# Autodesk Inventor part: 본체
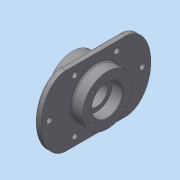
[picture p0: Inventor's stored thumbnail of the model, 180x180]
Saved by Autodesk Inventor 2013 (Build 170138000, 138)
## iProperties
Created: 2015-02
Part Number: 본체
Material: 일반
Document SubType Name: Modeling
Designer: Administrator
Density: 1 g/cm^3
Author: Administrator
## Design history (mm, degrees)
sketch "스케치1" dims "d51" = 50
  geometry: L1 (-154, 0)-(154, 0) reference; L2 (0, -98)-(0, 98) reference; L3 (60, 70)-(-60, 70); L4 (-60, 70)-(-60, -70); L5 (-60, -70)-(60, -70); L6 (60, -70)-(60, 70); 3 further points; 2 other entities
  constraints: 8 end point, 2 parallel, 2 vertical, 1 horizontal, 1 midpoint, 1 perpendicular, 1 symmetric about line, 10 other
  dimensions: "d1" = 140 distance of L4.end L3.end; "d3" = 120 distance between parallel lines of L4 L6
extrude "돌출1" new body sketch "스케치1" distance "d5" = 12; taper "d6" = 0 deg
sketch "스케치2"
  geometry: C1 r 50 at (0, 0); 1 further point
  constraints: 1 centre point, 1 coincident
  dimensions: "d7" = 100 diameter of C1
extrude "돌출2" join sketch "스케치2" distance "d9" = 23; taper "d11" = 0 deg; dims "d10" = 47, "d12" = 0
sketch "스케치3"
  geometry: L1 (0, 60)-(0, -60) reference; L2 (-35, 0)-(-35, 31); L3 (-35, 31)-(-13, 31); L4 (-13, 31)-(-13, 22.5); L5 (-13, 22.5)-(13, 22.5); L6 (13, 22.5)-(13, 31); L7 (13, 31)-(35, 31); L8 (35, 31)-(35, 0); L9 (-35, 50)-(-35, -50) reference; L10 (35, -50)-(35, 50) reference; 7 further points
  constraints: 14 end point, 4 midpoint, 3 parallel, 3 vertical, 2 point on line, 2 vertical alignment, 1 collinear, 1 perpendicular, 6 other
  dimensions: "d13" = 22 distance between parallel lines of L8 L6; "d15" = 22 distance between parallel lines of L4 L2; "d16" = 62 dimension on L3; "d17" = 62 dimension on L7; "d18" = 45 dimension on L5
revolve "회전1" sketch "스케치3" stored, may be unused: angle "d19" = 90 deg
sketch "스케치6" dims "d34" = 82
  geometry: L1 (0, 0)-(-28.991, 28.991); L2 (-98, 0)-(98, 0) reference; C1 r 50 at (0, 0) reference; 1 further point
  constraints: 2 coincident, 2 end point, 3 other
  dimensions: "d36" = 45 deg angle of L2 L1
hole "구멍1" sketch "스케치6" at (-28.991, 28.991) diameter "d38" = 4.917; stored, may be unused: countersink angle "d42" = 90 deg, drill point angle "d44" = 118 deg; dims "d39" = 10, "d40" = 4, "d41" = 2, "d43" = 13
node "작업 평면1"
sketch "스케치8" dims "d53" = 17
  geometry: L1 (70, 60)-(70, -60) reference; L2 (-70, -60)-(-70, 60) reference; L3 (53, 60)-(53, -60); L4 (-53, -60)-(-53, 60); L5 (0, -154)-(0, 154) reference; L6 (-98, 0)-(98, 0) reference; L7 (-82.976, 42)-(82.976, 42); C1 r 10 at (0, 93); C2 r 50 at (0, 0) reference; C3 r 10 at (-53, 42); C4 r 10 at (53, 42); A1 r 93 centre (0, 0) between (0, 93) and (82.976, 42); 2 further points; 2 other entities
  constraints: 6 end point, 5 point on line, 4 centre point, 4 parallel, 3 point on circle, 1 coincident, 1 horizontal alignment, 8 other
  dimensions: "d55" = 20 diameter of C1; "d62" = 42 distance between parallel lines of L6 L7; "d63" = 20 diameter of C4; "d64" = 20 diameter of C3
extrude "돌출6" join sketch "스케치8" distance "d65" = 5; taper "d66" = 0 deg
sketch "스케치9"
  geometry: C1 r 10 at (0, 0) reference; C2 r 5.5 at (0, 0); C3 r 10 at (-53, -135) reference; C4 r 10 at (0, -186) reference; C5 r 10 at (53, -135) reference; C6 r 10 at (-53, -51) reference; C7 r 10 at (0, 0) reference; C8 r 10 at (53, -51) reference; C9 r 22.5 at (0, -93) reference; C10 r 50 at (0, -93) reference; C11 r 5.5 at (-53, -51); C12 r 5.5 at (53, -51); C13 r 5.5 at (53, -135); C14 r 5.5 at (0, -186); C15 r 5.5 at (-53, -135); 1 further point
  constraints: 6 centre point, 6 coincident, 5 equal radius
  dimensions: "d67" = 11 diameter of C2
extrude "돌출7" cut sketch "스케치9" stored distance "d69" = 5; taper "d70" = 0 deg
fillet "모깎기1" dims "d71" = 0.3
fillet "모깎기2" dims "d72" = 3
sketch "스케치10"
  geometry: C1 r 53 at (0, 0) reference; 1 further point
  constraints: 1 vertical alignment, 1 other
  dimensions: "d73" = 65 distance of C1.centre point (0, 65)
feature "엠보싱1" sketch "스케치10" dims "d1" = 140, "d3" = 120, "d13" = 22, "d15" = 22, "d16" = 62, "d17" = 62, "d18" = 45, "d51" = 50, "d74" = 1, "d75" = 0
chamfer "모따기1" distance "d76" = 1; stored, may be unused: second distance "d77" = 2, angle "d78" = 45 deg
node "솔리드1"
pattern_circular "원형 패턴1" dims angle "d46" = 360 deg
mirror "대칭1"
mirror "대칭2"
node "절단 모서리 투영4"
